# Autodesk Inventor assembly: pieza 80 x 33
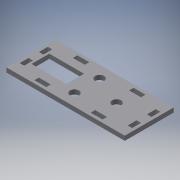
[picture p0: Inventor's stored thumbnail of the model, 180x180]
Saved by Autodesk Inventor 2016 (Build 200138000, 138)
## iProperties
Created: 2016-06
Part Number: pieza 80 x 33
Material: Genérico
Document SubType Name: Assembly
Designer: adm
Author: adm
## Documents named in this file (2)
- C:\Users\adm\Desktop\pieza 80 x 33.iam
- C:\Users\adm\Desktop\Base\Pieza19.ipt
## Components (1 placed, 1 different names)
1. Pieza19:1
